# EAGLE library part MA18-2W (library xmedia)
PIN HEADER
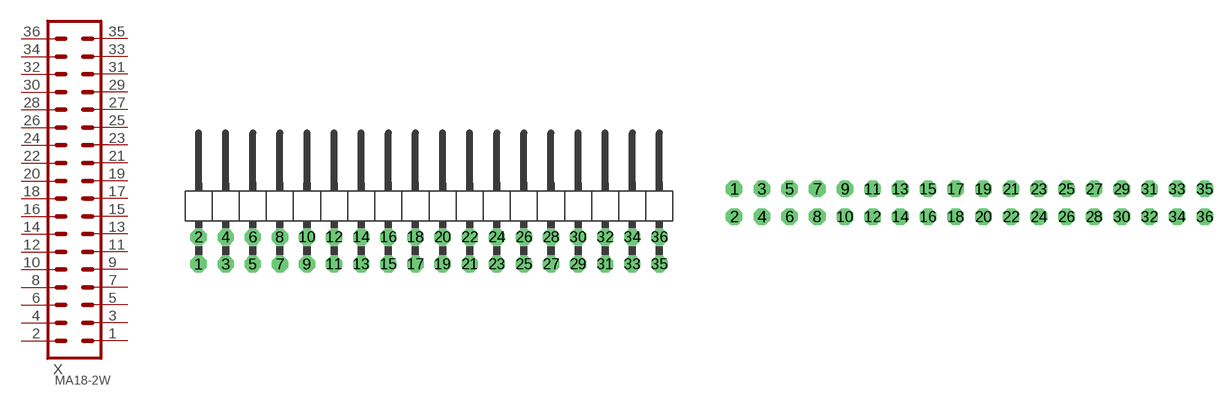
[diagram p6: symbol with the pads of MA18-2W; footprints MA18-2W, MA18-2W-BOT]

Designator prefix X

## MA18-2W  [MA18-2W]
1  1  pas
2  2  pas
3  3  pas
4  4  pas
5  5  pas
6  6  pas
7  7  pas
8  8  pas
9  9  pas
10  10  pas
11  11  pas
12  12  pas
13  13  pas
14  14  pas
15  15  pas
16  16  pas
17  17  pas
18  18  pas
19  19  pas
20  20  pas
21  21  pas
22  22  pas
23  23  pas
24  24  pas
25  25  pas
26  26  pas
27  27  pas
28  28  pas
29  29  pas
30  30  pas
31  31  pas
32  32  pas
33  33  pas
34  34  pas
35  35  pas
36  36  pas

## MA18-2WBOTTOM  [MA18-2W-BOT]
Pads as for MA18-2W

## MA18-2WH  [MA18-2]
Pads as for MA18-2W

## Footprint MA18-2W (pad centres in mm)
PIN HEADER
drill 1.016 octagon: 1 -21.59,-1.27; 2 -21.59,1.27; 3 -19.05,-1.27; 4 -19.05,1.27; 5 -16.51,-1.27; 6 -16.51,1.27; 7 -13.97,-1.27; 8 -13.97,1.27; 9 -11.43,-1.27; 10 -11.43,1.27; 11 -8.89,-1.27; 12 -8.89,1.27; 13 -6.35,-1.27; 14 -6.35,1.27; 15 -3.81,-1.27; 16 -3.81,1.27; 17 -1.27,-1.27; 18 -1.27,1.27; 19 1.27,-1.27; 20 1.27,1.27; 21 3.81,-1.27; 22 3.81,1.27; 23 6.35,-1.27; 24 6.35,1.27; 25 8.89,-1.27; 26 8.89,1.27; 27 11.43,-1.27; 28 11.43,1.27; 29 13.97,-1.27; 30 13.97,1.27; 31 16.51,-1.27; 32 16.51,1.27; 33 19.05,-1.27; 34 19.05,1.27; 35 21.59,-1.27; 36 21.59,1.27

## Footprint MA18-2W-BOT (pad centres in mm)
drill 1.016 octagon: 1 -21.59,-3.81; 2 -21.59,-6.35; 3 -19.05,-3.81; 4 -19.05,-6.35; 5 -16.51,-3.81; 6 -16.51,-6.35; 7 -13.97,-3.81; 8 -13.97,-6.35; 9 -11.43,-3.81; 10 -11.43,-6.35; 11 -8.89,-3.81; 12 -8.89,-6.35; 13 -6.35,-3.81; 14 -6.35,-6.35; 15 -3.81,-3.81; 16 -3.81,-6.35; 17 -1.27,-3.81; 18 -1.27,-6.35; 19 1.27,-3.81; 20 1.27,-6.35; 21 3.81,-3.81; 22 3.81,-6.35; 23 6.35,-3.81; 24 6.35,-6.35; 25 8.89,-3.81; 26 8.89,-6.35; 27 11.43,-3.81; 28 11.43,-6.35; 29 13.97,-3.81; 30 13.97,-6.35; 31 16.51,-3.81; 32 16.51,-6.35; 33 19.05,-3.81; 34 19.05,-6.35; 35 21.59,-3.81; 36 21.59,-6.35

## Footprint MA18-2 (pad centres in mm)
PIN HEADER
drill 1.016 octagon: 1 -21.59,-1.27; 2 -21.59,1.27; 3 -19.05,-1.27; 4 -19.05,1.27; 5 -16.51,-1.27; 6 -16.51,1.27; 7 -13.97,-1.27; 8 -13.97,1.27; 9 -11.43,-1.27; 10 -11.43,1.27; 11 -8.89,-1.27; 12 -8.89,1.27; 13 -6.35,-1.27; 14 -6.35,1.27; 15 -3.81,-1.27; 16 -3.81,1.27; 17 -1.27,-1.27; 18 -1.27,1.27; 19 1.27,-1.27; 20 1.27,1.27; 21 3.81,-1.27; 22 3.81,1.27; 23 6.35,-1.27; 24 6.35,1.27; 25 8.89,-1.27; 26 8.89,1.27; 27 11.43,-1.27; 28 11.43,1.27; 29 13.97,-1.27; 30 13.97,1.27; 31 16.51,-1.27; 32 16.51,1.27; 33 19.05,-1.27; 34 19.05,1.27; 35 21.59,-1.27; 36 21.59,1.27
